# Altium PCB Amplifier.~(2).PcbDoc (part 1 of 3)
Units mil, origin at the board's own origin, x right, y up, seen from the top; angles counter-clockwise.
Board outline 9055.12 x 4724.41 mil, 2 copper layers (Top Layer, Bottom Layer); 154 components, 83 nets, 405 pads, 1525 vias.
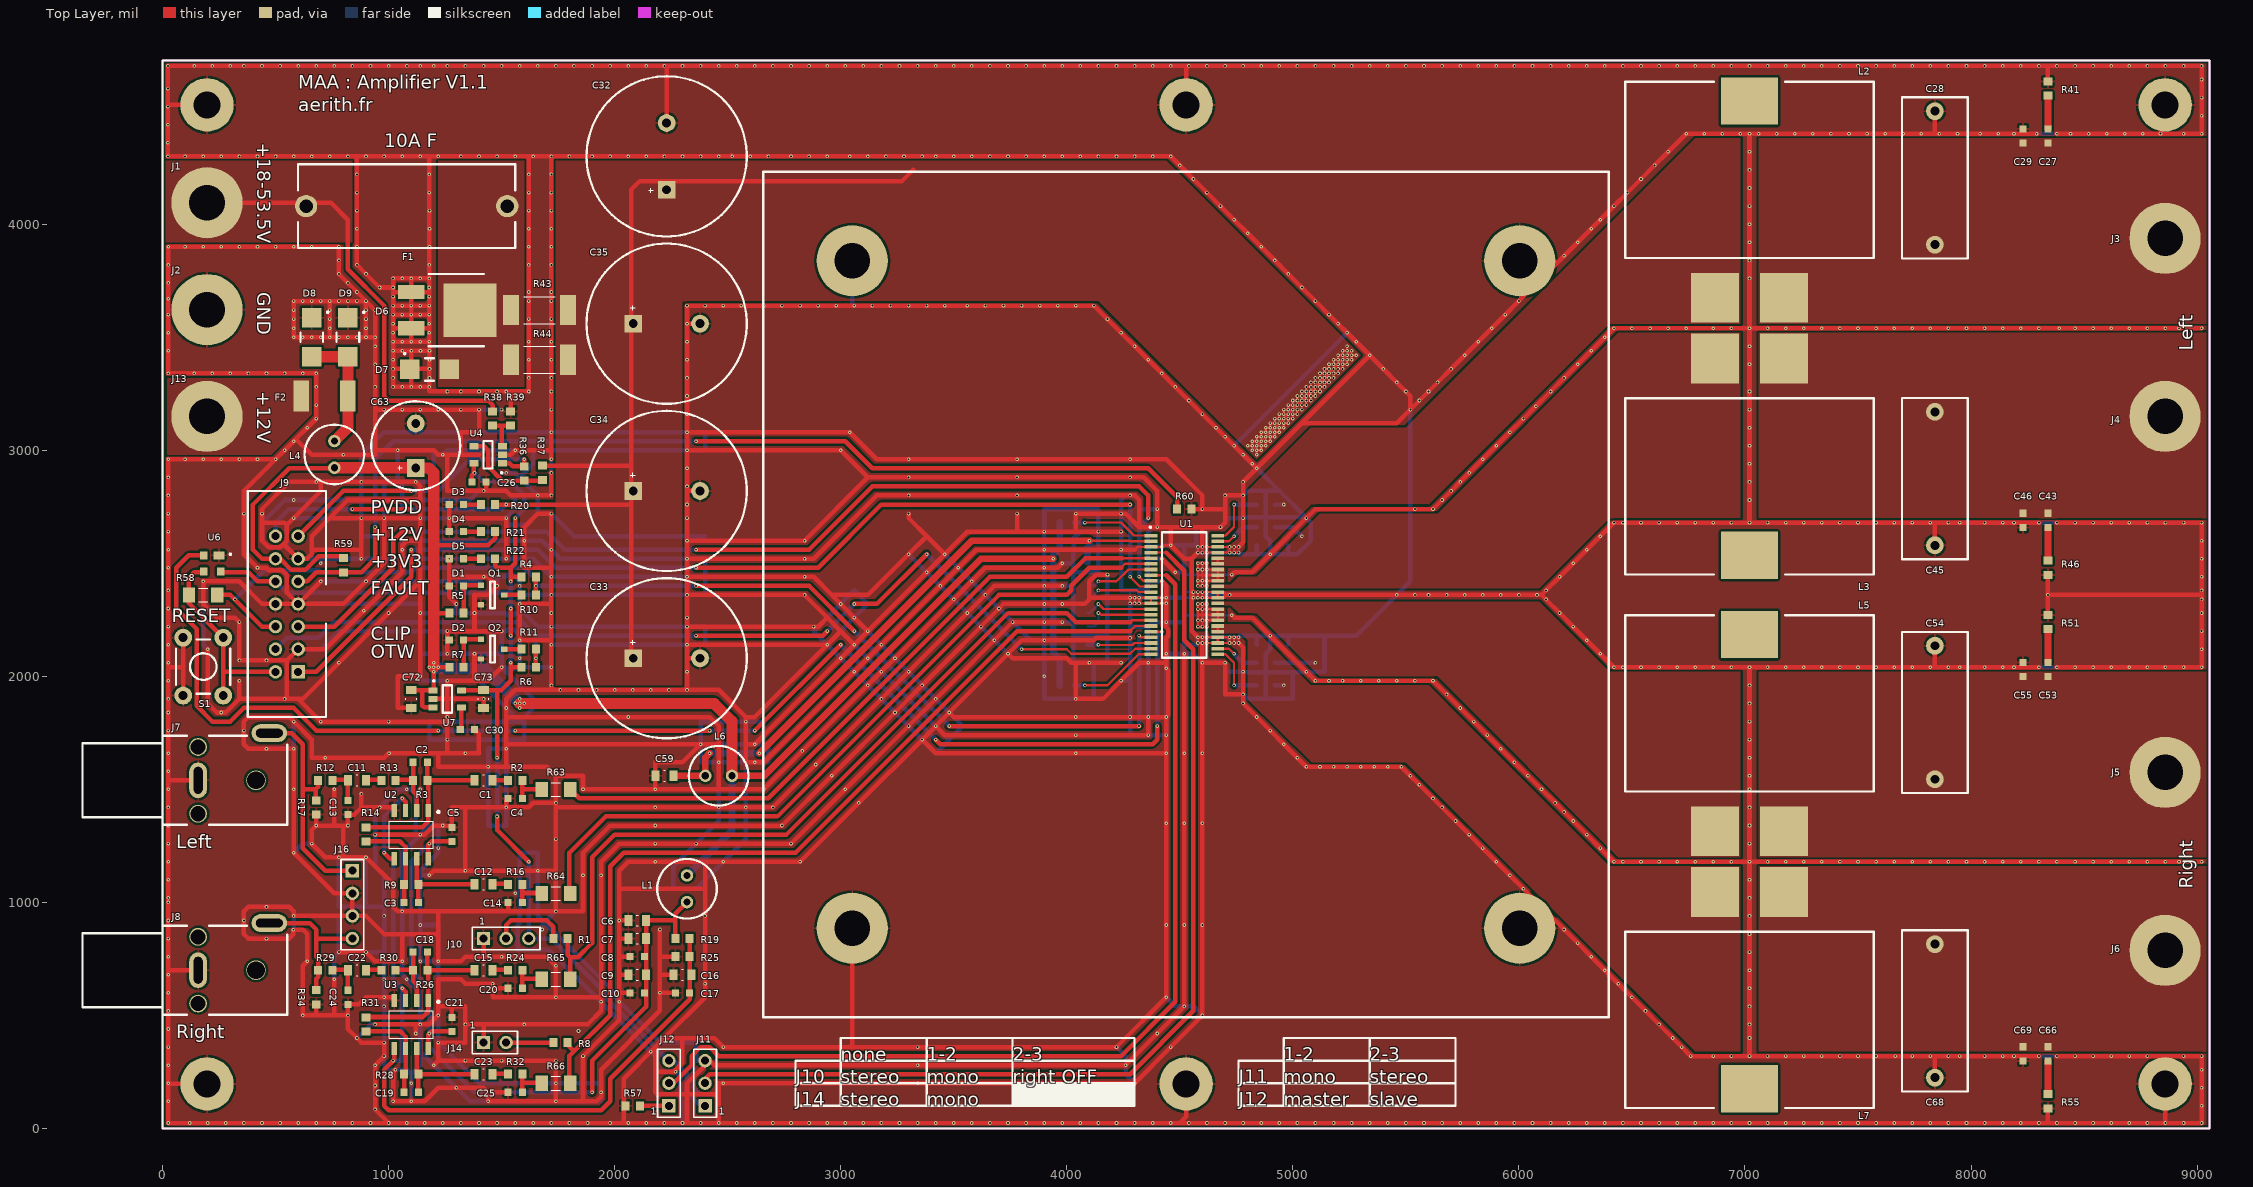
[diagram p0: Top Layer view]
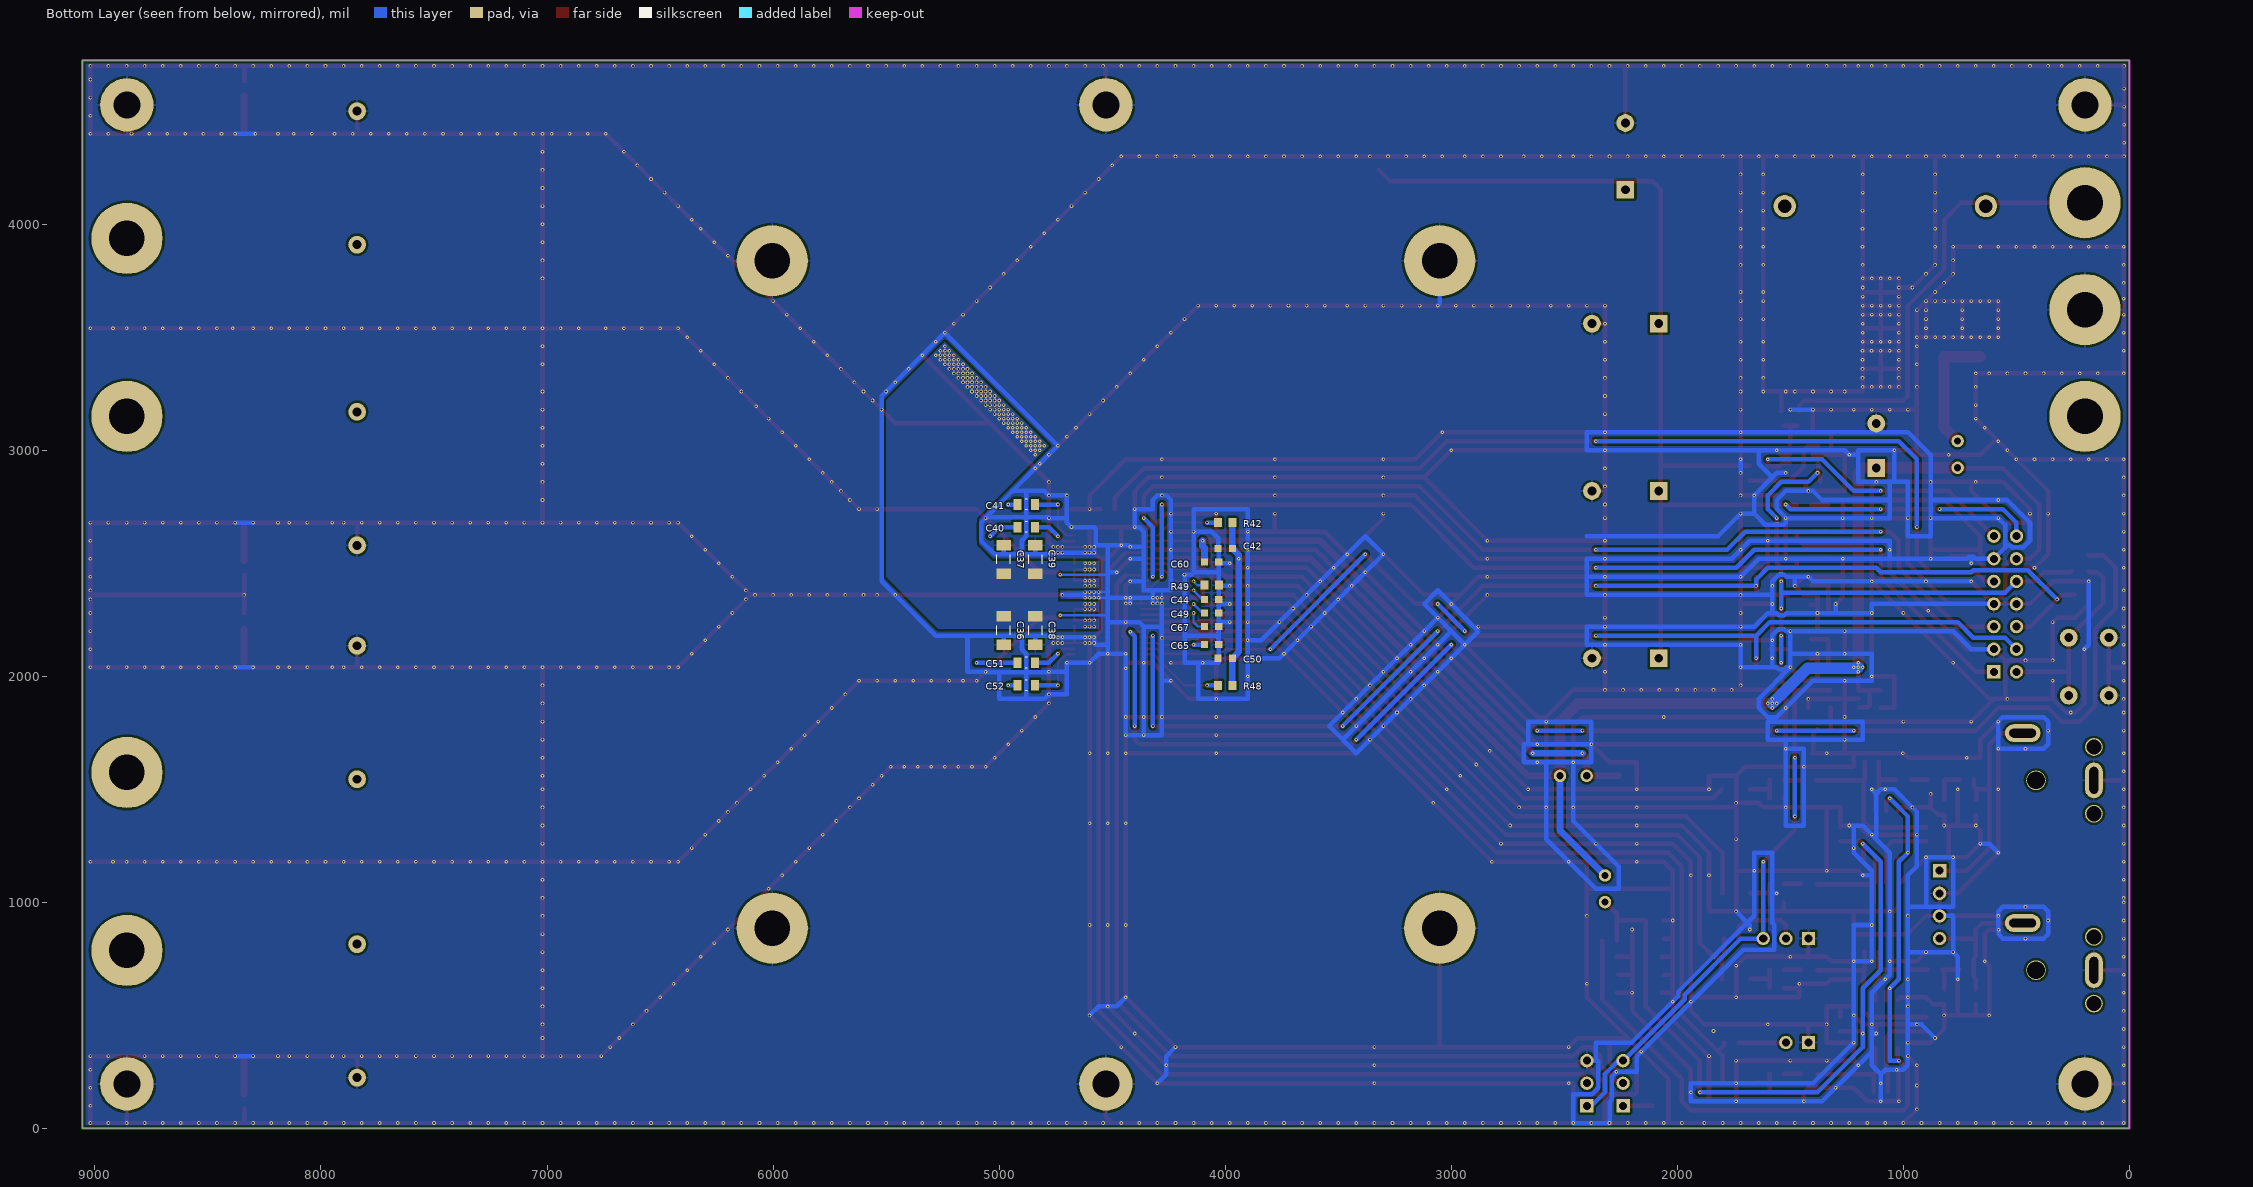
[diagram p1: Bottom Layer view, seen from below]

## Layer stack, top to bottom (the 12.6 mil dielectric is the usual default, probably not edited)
Top Solder: solder mask 0.4, Solder Resist, Dk 3.5
Top Layer: signal copper 1.4
Dielectric 1: dielectric 12.6, FR-4, Dk 4.8
Bottom Layer: signal copper 1.4
Bottom Solder: solder mask 0.4, Solder Resist, Dk 3.5

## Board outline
0,0 9055.12,0 9055.12,4724.41 0,4724.41

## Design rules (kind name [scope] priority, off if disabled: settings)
Clearance [All] p1: gap=10 ignorepadtopadclearanceinfootprint=FALSE except(0: Arc-Hole Track-Hole SMDPad-Hole THPad-Hole Via-Hole Fill-Hole Poly-Hole Region-Hole Text-Hole; 9: Arc-Arc Arc-Track Arc-SMDPad Track-Track Track-SMDPad SMDPad-SMDPad; 29: THPad-THPad)
ComponentClearance U1 [InComponent('U1')] p1: gap=20 collisioncheckmode=3 verticalgap=0 showdistances=TRUE
ComponentClearance [All] p2: gap=19.68 collisioncheckmode=3 verticalgap=3.94 showdistances=TRUE
Height [All] p1: minheight=0 maxheight=2000 prefheight=500
HoleSize [All] p1: absolutevalues=TRUE maxlimit=393.7 minlimit=7.87 maxpercent=80.000 minpercent=20.000
MinimumSolderMaskSliver [All] p1: minsoldermaskwidth=1
PlaneConnect [All] p1: planeconnectstyle=Direct reliefexpansion=20 reliefentries=4 reliefconductorwidth=20 reliefairgap=20
PolygonConnect GND [InNet('GND')] p1: thpad.connectstyle=Relief thpad.reliefconductorwidth=10 thpad.reliefentries=4 thpad.polygonreliefangle="90 Angle" thpad.airgapwidth=10 smdpad.connectstyle=Relief smdpad.reliefconductorwidth=10 smdpad.reliefentries=4 smdpad.polygonreliefangle="90 Angle" smdpad.airgapwidth=10 via.connectstyle=Direct via.reliefconductorwidth=10 via.reliefentries=4 via.polygonreliefangle="90 Angle" via.airgapwidth=10
PolygonConnect DirectConnect [All] p2: connectstyle=Direct reliefconductorwidth=10 reliefentries=4 polygonreliefangle="90 Angle" airgapwidth=10
RoomDefinition Extension [InComponentClass('Extension')] p1: confinementstyle=ConfineIn formatcopy=TRUE lockcomponents=FALSE outline 360,1800 840,1800 840,2840 360,2840
RoomDefinition Amplifier_12V [InComponentClass('Amplifier_12V')] p2: confinementstyle=ConfineIn formatcopy=TRUE lockcomponents=FALSE outline 2140,1420 2600,1420 2600,1700 2140,1700
RoomDefinition Audio_in [InComponentClass('Audio_in')] p3: confinementstyle=ConfineIn formatcopy=TRUE lockcomponents=TRUE outline 760,1220 920,1220 920,760 760,760
RoomDefinition Amplifier_conf [InComponentClass('Amplifier_conf')] p4: confinementstyle=ConfineIn formatcopy=TRUE lockcomponents=TRUE outline 2000,40 2460,40 2460,380 2000,380
RoomDefinition Amplifier_capa [InComponentClass('Amplifier_capa')] p5: confinementstyle=ConfineIn formatcopy=TRUE lockcomponents=TRUE outline 1840,1700 2600,1700 2600,4680 1840,4680
RoomDefinition Thermistance [InComponentClass('Thermistance')] p6: confinementstyle=ConfineIn formatcopy=TRUE lockcomponents=TRUE outline 4460,2840 4580,2840 4580,2700 4460,2700
RoomDefinition Amplifier_core [InComponentClass('Amplifier_core')] p7: confinementstyle=ConfineIn formatcopy=TRUE lockcomponents=TRUE outline 3920,1920 5040,1920 5040,2800 3920,2800
RoomDefinition Status [InComponentClass('Status')] p8: confinementstyle=ConfineIn formatcopy=TRUE lockcomponents=FALSE outline 1160,2800 1160,2000 1700,2000 1700,2800
RoomDefinition Reset [InComponentClass('Reset')] p9: confinementstyle=ConfineIn formatcopy=TRUE lockcomponents=FALSE outline 40,1860 320,1860 320,2560 40,2560
RoomDefinition PVDD_supply [InComponentClass('PVDD_supply')] p10: confinementstyle=ConfineIn formatcopy=TRUE lockcomponents=TRUE outline 0,3260 1840,3260 1840,4280 0,4280
RoomDefinition Pre-amp_supply [InComponentClass('Pre-amp_supply')] p11: confinementstyle=ConfineIn formatcopy=TRUE lockcomponents=FALSE outline 2020,1200 2020,560 2480,560 2480,1200
RoomDefinition Pre-amp_right [InComponentClass('Pre-amp_right')] p12: confinementstyle=ConfineIn formatcopy=TRUE lockcomponents=FALSE outline -380,120 1860,120 1860,960 -380,960
RoomDefinition Pre-amp_left [InComponentClass('Pre-amp_left')] p13: confinementstyle=ConfineIn formatcopy=TRUE lockcomponents=TRUE outline -380,960 1860,960 1860,1800 -380,1800
RoomDefinition Output_D [InComponentClass('Output_D')] p14: confinementstyle=ConfineIn formatcopy=TRUE lockcomponents=FALSE outline 6440,20 9038.72,20 9038.72,1180 6440,1180
RoomDefinition Output_C [InComponentClass('Output_C')] p15: confinementstyle=ConfineIn formatcopy=TRUE lockcomponents=FALSE outline 6440,1180 9040,1180 9040,2360 6440,2360
RoomDefinition Output_B [InComponentClass('Output_B')] p16: confinementstyle=ConfineIn formatcopy=TRUE lockcomponents=FALSE outline 6440,2360 9040,2360 9040,3540 6440,3540
RoomDefinition Output_A [InComponentClass('Output_A')] p17: confinementstyle=ConfineIn formatcopy=TRUE lockcomponents=FALSE outline 6440,3540 9040,3540 9040,4700 6440,4700
RoomDefinition Current_sense [InComponentClass('Current_sense')] p18: confinementstyle=ConfineIn formatcopy=TRUE lockcomponents=TRUE outline 1340,2808.5 1720,2808.5 1720,3268.5 1340,3268.5
RoomDefinition 12V_supply [InComponentClass('12V_supply')] p19: confinementstyle=ConfineIn formatcopy=TRUE lockcomponents=TRUE outline 20,3640 20,2800 1340,2800 1340,3640
RoomDefinition 3V3_supply [InComponentClass('3V3_supply')] p20: confinementstyle=ConfineIn formatcopy=TRUE lockcomponents=TRUE outline 1060,1720 1540,1720 1540,1999.37 1060,1999.37
RoutingVias [All] p1: holewidth=7.87 width=15.75 viastyle="Through Hole" minholewidth=7.87 minwidth=15.75 maxholewidth=15.75 maxwidth=31.5
SilkToSilkClearance [All] p1: silktosilkclearance=0
SolderMaskExpansion [All] p1: expansion=4
Width [All] p1: maxlimit=500 minlimit=10 preferedwidth=10
24 further rules are at their usual default settings.

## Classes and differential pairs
component class Extension: J9 R59
component class Audio_in: J16
component class Amplifier_conf: J11 J12 R57
component class Amplifier_capa: C32 C33 C34 C35
component class Thermistance: R60
component class Amplifier_core: C36 C37 C38 C39 C40 C41 C42 C44 C49 C50 C51 C52 C60 C65 C67 R42 R48 R49 U1
component class Status: D1 D2 D3 D4 D5 Q1 Q2 R4 R5 R6 R7 R10 R11 R20 R21 R22
component class Reset: R58 S1 U6
component class PVDD_supply: D6 D7 F1 J1 J2 R43 R44
component class Pre-amp_supply: C6 C7 C8 C9 C10 C16 C17 L1 R19 R25
component class Pre-amp_right: C15 C18 C19 C20 C21 C22 C23 C24 C25 J8 J10 J14 R1 R8 R24 R26 R28 R29 R30 R31 R32 R34 R65 R66 U3
component class Pre-amp_left: C1 C2 C3 C4 C5 C11 C12 C13 C14 J7 R2 R3 R9 R12 R13 R14 R16 R17 R63 R64 U2
component class Output_D: C66 C68 C69 J6 L7 R55
component class Output_C: C53 C54 C55 J5 L5 R51
component class Output_B: C43 C45 C46 J4 L3 R46
component class Output_A: C27 C28 C29 J3 L2 R41
component class Current_sense: C26 R36 R37 R38 R39 U4
component class 12V_supply: C63 D8 D9 F2 J13 L4
component class 3V3_supply: C30 C72 C73 U7
component class Amplifier_12V: C59 L6

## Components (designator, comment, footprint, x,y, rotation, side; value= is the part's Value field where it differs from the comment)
C1 "10µF" C0805 1420,1540 r0 top
C2 "22pF" C0603 1140,1620 r0 top
C3 "22pF" C0603 1100,1000 r0 top
C4 "100pF" C0603 1560,1460 r180 top
C5 "100nF" C0603 1280,1300 r90 top
C6 "10µF" C0805 2100,920 r180 top
C7 "10µF" C0805 2100,840 r180 top
C8 "100nF" C0603 2100,760 r180 top
C9 "10µF" C0805 2100,680 r180 top
C10 "100nF" C0603 2100,600 r180 top
C11 "10µF" C0805 860,1540 r0 top
C12 "10µF" C0805 1420,1080 r0 top
C13 "100pF" C0603 820,1420 r270 top
C14 "100pF" C0603 1560,1000 r180 top
C15 "10µF" C0805 1420,700 r0 top
C16 "10µF" C0805 2300,680 r180 top
C17 "100nF" C0603 2300,600 r180 top
C18 "22pF" C0603 1140,780 r0 top
C19 "22pF" C0603 1100,160 r0 top
C20 "100pF" C0603 1560,620 r180 top
C21 "100nF" C0603 1280,460 r90 top
C22 "10µF" C0805 860,700 r0 top
C23 "10µF" C0805 1420,240 r0 top
C24 "100pF" C0603 820,580 r270 top
C25 "100pF" C0603 1560,160 r180 top
C26 "100nF" C0603 1400,2860 r0 top
C27 "10nF 100V" C0603 8340,4390 r90 top
C28 "680nF 250V" CAP_15 7840,4204.72 r90 top
C29 "1nF 100V" C0603 8230,4390 r90 top
C30 "10nF 100V" C0603 1348.54,1765 r0 top
C32 "2200µF 63V" CAP_18X7.5 2230,4300 r90 top
C33 "2200µF 63V" CAP_18X7.5 2230,2080 r0 top
C34 "2200µF 63V" CAP_18X7.5 2230,2820 r0 top
C35 "2200µF 63V" CAP_18X7.5 2230,3560 r0 top
C36 "1µF 100V" C1206 4980,2202.99 r270 bottom
C37 "1µF 100V" C1206 4980,2517.01 r90 bottom
C38 "1µF 100V" C1206 4840,2202.99 r270 bottom
C39 "1µF 100V" C1206 4840,2517.01 r90 bottom
C40 "33nF 100V" C0805 4880,2660 r180 bottom
C41 "33nF 100V" C0805 4880,2760 r180 bottom
C42 "100nF" C0603 4000,2565.45 r0 bottom
C43 "10nF 100V" C0603 8340,2690 r270 top
C44 "1µF" C0603 4060,2340 r0 bottom
C45 "680nF 250V" CAP_15 7840,2874.72 r270 top
C46 "1nF 100V" C0603 8230,2690 r270 top
C49 "1µF" C0603 4060,2280 r0 bottom
C50 "100nF" C0603 4000,2080 r0 bottom
C51 "33nF 100V" C0805 4880,2060 r0 bottom
C52 "33nF 100V" C0805 4880,1960 r0 bottom
C53 "10nF 100V" C0603 8340,2030 r90 top
C54 "680nF 250V" CAP_15 7840,1840 r90 top
C55 "1nF 100V" C0603 8230,2030 r90 top
C59 "10µF" C0805 2220,1560 r180 top
C60 "100nF" C0603 4060,2506.26 r180 bottom
C63 "1000µF 16V" CAP_10x5 1120,3020 r90 top
C65 "100nF" C0603 4060,2140 r180 bottom
C66 "10nF 100V" C0603 8340,330 r270 top
C67 "1µF" C0603 4060,2220 r0 bottom
C68 "680nF 250V" CAP_15 7840,520 r270 top
C69 "1nF 100V" C0603 8230,330 r270 top
C72 "10µF" C0805 1100,1900 r270 top
C73 "10µF" C0805 1420,1900 r270 top
D1 "Red" C0603 1300,2400 r180 top
D2 "Yellow" C0603 1300,2160 r180 top
D3 "Green" C0603 1300,2760 r180 top
D4 "Green" C0603 1300,2640 r180 top
D5 "Green" C0603 1300,2520 r180 top
D6 "15A" DPAK 1300,3620 r270 top
D7 "56V" DO-214AC 1181.01,3357.43 r0 top
D8 "12V" DO-214AC 660,3500 r270 top
D9 "2A" DO-214AC 820,3500 r270 top
F1 "10A F" "FUSE OLDER" 1080,4080 r0 top
F2 "1.1A PTC" MC362XX 716.46,3240 r0 top
J1 "M4 screw" HOLE_4#1 196.85,4094.49 r0 top
J2 "M4 screw" HOLE_4#2 196.85,3582.68 r0 top
J3 "M4 screw" HOLE_4#1 8858.27,3937.01 r0 top
J4 "M4 screw" HOLE_4#1 8858.27,3149.61 r0 top
J5 "M4 screw" HOLE_4#1 8858.27,1574.8 r0 top
J6 "M4 screw" HOLE_4#1 8858.27,787.4 r0 top
J7 "RCA" CON_RCA 0,1540 r90 top
J8 "RCA" CON_RCA 0,700 r90 top
J9 "2x7x2.54" CON_header_2x7 550,2320 r90 top
J10 "3x2.54" HDR1X3 1420,840 r0 top
J11 "3x2.54" HDR1X3 2400,100 r90 top
J12 "3x2.54" HDR1X3 2240,100 r90 top
J13 "M4 screw" HOLE_4#1 196.85,3149.61 r0 top
J14 "2x2.54" HDR1X2 1420,380 r0 top
J16 "4x2.54 lock" HDR1X4 840,1140 r270 top
L1 "10µH 1A" SELF_6.7x3 2320,1060 r270 top
L2 "SER2915L-682KL" SELF_SMD_SER2915X 7020,4240 r0 top
L3 "SER2915L-682KL" SELF_SMD_SER2915X 7020,2840 r180 top
L4 "10µH 1A" SELF_6.7x3 760,2981.58 r270 top
L5 "SER2915L-682KL" SELF_SMD_SER2915X 7020,1880 r0 top
L6 "10µH 1A" SELF_6.7x3 2460,1560 r180 top
L7 "SER2915L-682KL" SELF_SMD_SER2915X 7020,480 r180 top
Q1 "BSH108" SOT-23-GSD 1460,2360 r0 top
Q2 "BSH108" SOT-23-GSD 1460,2120 r0 top
R1 "10k" R0603 1760,840 r0 top
R2 "100" R0603 1560,1540 r180 top
R3 "10k" R0603 1140,1540 r180 top
R4 "10k" R0603 1620,2440 r0 top
R5 "1k" R0603 1300,2280 r0 top
R6 "10k" R0603 1620,2040 r0 top
R7 "1k" R0603 1300,2040 r0 top
R8 "10k" R0603 1760,380 r180 top
R9 "10k" R0603 1100,1080 r180 top
R10 "100" R0603 1620,2360 r0 top
R11 "100" R0603 1620,2120 r0 top
R12 "100" R0603 720,1540 r180 top
R13 "10k" R0603 1000,1540 r180 top
R14 "10k" R0603 900,1300 r90 top
R16 "100" R0603 1560,1080 r180 top
R17 "100k" R0603 680,1420 r270 top
R19 "10k" R0603 2300,840 r0 top
R20 "4k7" R0603 1440,2760 r180 top
R21 "1k" R0603 1440,2640 r180 top
R22 "100" R0603 1440,2520 r180 top
R24 "100" R0603 1560,700 r180 top
R25 "10k" R0603 2300,760 r180 top
R26 "10k" R0603 1140,700 r180 top
R28 "10k" R0603 1100,240 r180 top
R29 "100" R0603 720,700 r180 top
R30 "10k" R0603 1000,700 r180 top
R31 "10k" R0603 900,460 r90 top
R32 "100" R0603 1560,240 r180 top
R34 "100k" R0603 680,580 r270 top
R36 "470k" R0603 1600,2897.01 r270 top
R37 "10k" R0603 1680,2900 r270 top
R38 "10k" R0603 1460,3140 r270 top
R39 "470k" R0603 1540,3140 r90 top
R41 "3R3" R0603 8340,4600 r90 top
R42 "3R3" R0603 4000,2680 r180 bottom
R43 "10m 1W" R2512 1667.22,3620 r0 top
R44 "10m 1W" R2512 1667.22,3400 r0 top
R46 "3R3" R0603 8340,2480 r270 top
R48 "3R3" R0603 4000,1960 r180 bottom
R49 "30k" R0603 4060,2403.13 r0 bottom
R51 "3R3" R0603 8340,2240 r90 top
R55 "3R3" R0603 8340,120 r270 top
R57 "10k" R0603 2080,100 r0 top
R58 "R0" R1206 180,2360 r0 top
R59 "30k" R0603 800,2491.5 r270 top
R60 "10k CTN" R0603 4520,2740 r180 top
R63 "R0" R1206 1740,1500 r180 top
R64 "R0" R1206 1740,1040 r180 top
R65 "R0" R1206 1740,660 r180 top
R66 "R0" R1206 1740,200 r180 top
S1 "SW-PB" BP_PCB 180,2043.05 r90 top
U1 "TPA3255" TSSOP-44 4520,2360 r0 top locked
U2 "OPA1652" SOIC-8 1100,1300 r270 top
U3 "OPA1652" SOIC-8 1100,460 r270 top
U4 "MCP6001" SOT-23-5 1440,2980 r270 top
U6 "STM811T" SOT143-4 220,2500 r270 top
U7 "LP2985-33DBVR" SOT-23-5 1260,1900 r90 top

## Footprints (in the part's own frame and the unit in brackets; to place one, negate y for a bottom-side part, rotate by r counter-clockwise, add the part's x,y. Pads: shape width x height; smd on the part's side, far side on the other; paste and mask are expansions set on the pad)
BP_PCB [mm] "Mini bouton poussoir sur PCB"
  round 2 hole 1: 1(-3.25,2.25) 1(3.25,2.25) 2(-3.25,-2.25) 2(3.25,-2.25)
  silkscreen extent -3.05,-3.05 3.05,3.05, body extent -3.5,-3 3.5,3, height 5
C0603 [mm]
  rect 0.8x0.8 smd: 1(-0.8,0) 2(0.8,0)
  body extent -0.8,-0.4 0.8,0.4, height 0.8
C0805 [mm]
  rect 0.9x1.2 smd: 1(-1,0) 2(1,0)
  silkscreen extent -0.1,-0.6 0.1,0.6, body extent -1,-0.6 1,0.6, height 1.2
C1206 [mm]
  rect 1.2x1.6 smd: 1(-1.6,0) 2(1.6,0)
  silkscreen extent -0.51,-0.76 0.51,0.76, body extent -1.6,-0.8 1.6,0.8, height 1.6
CAP_10x5 [mm] "Capacitor throug hole dia=10mm, H=16mm, spacing=5mm"
  rect 2x2 hole 1: 1(-2.5,0)
  round 2 hole 1: 2(2.5,0)
  silkscreen extent -5,-5 5,5, body extent -5,-5 5,5, height 16
CAP_15 [mm] "Film capacitor, step 15mm"
  round 2 hole 1: 1(-7.5,0) 2(7.5,0)
  silkscreen extent -9.05,-3.7 9.05,3.7, body extent -9.05,-3.7 9.05,3.7, height 19
CAP_18X7.5 [mm] "Capacitor throug hole dia=18mm, H=35.5mm, spacing=7.5mm"
  rect 2x2 hole 1: 1(-3.75,0)
  round 2 hole 1: 2(3.75,0)
  silkscreen extent -9,-9 9,9, body extent -9,-9 9,9, height 35.5
CON_header_2x7 [mm] "2x7x2.54mm with lock"
  rect 1.5x1.5 hole 0.9: 1(-7.62,-1.27)
  round 1.5 hole 0.9: 2(-7.62,1.27) 3(-5.08,-1.27) 4(-5.08,1.27) 5(-2.54,-1.27) 6(-2.54,1.27) 7(0,-1.27) 8(0,1.27) 9(2.54,-1.27) 10(2.54,1.27) 11(5.08,-1.27) 12(5.08,1.27) 13(7.62,-1.27) 14(7.62,1.27)
  silkscreen extent -12.7,-4.4 12.7,4.4, body extent -12.7,-4.4 12.7,4.4, height 9
CON_RCA [mm] "JEITA RC-5231"
  oval 4x2 hole 1 slot 3 at 0 deg: 1(0,-4)
  oval 2x4 hole 1 slot 3 at 90 deg: 2(5.3,-12)
  round 2 hole 1.7: ""(-3.75,-4) ""(3.75,-4)
  round 2.2 hole 2: ""(0,-10.5)
  silkscreen extent -5,-14 5,9, body extent -5,-14 5,9, height 13
DO-214AC [mm]
  rect 2.2x2.2 smd: 1(-2.2,0) 2(2.2,0)
  silkscreen extent -2.89,-1.27 0.51,1.88, body extent -2.75,-1.4 2.75,1.4, height 2.3
DPAK [mm] "DPAK"
  rect 1.6x3 smd: 1(-2.032,-5.08) 3(2.032,-5.08)
  rect 6x6 smd: 2(0,1.524)
  silkscreen extent -4.06,-3.11 4.06,3.11, body extent -3.36,-3.11 3.36,3.11, height 2.38
"FUSE OLDER" [mm] "MULTICOMP - MCHTC-100M - 5X20mm"
  round 2.5 hole 1.5: 1(-11.3,0) 2(11.3,0)
  silkscreen extent -12.2,-4.7 12.2,4.7, body extent -12.2,-4.7 12.2,4.7, height 13.3
HDR1X2 [mm] "Connector; Header; 2 Position"
  rect 1.5x1.5 hole 0.9: 1(0,0)
  round 1.5 hole 0.9: 2(2.54,0)
  silkscreen extent -1.27,-1.27 3.81,1.27
HDR1X3 [mm] "Connector; Header; 3 Position"
  rect 1.5x1.5 hole 0.9: 1(0,0)
  round 1.5 hole 0.9: 2(2.54,0) 3(5.08,0)
  silkscreen extent -1.27,-1.27 6.35,1.27
HDR1X4 [mm] "Connector; Header; 4 Position"
  rect 1.5x1.5 hole 0.9: 1(0,0)
  round 1.5 hole 0.9: 2(2.54,0) 3(5.08,0) 4(7.62,0)
  silkscreen extent -1.27,-1.27 8.89,1.27
HOLE_4#1 [mm] "Hole for M4 screw"
  round 8 hole 4: 1(0,0)
HOLE_4#2 [mm] "Hole for M4 screw"
  round 8 hole 4: 1(0,1)
MC362XX [mm] "Fuse PTC"
  rect 1.78x3.5 smd: 1(-2.615,0) 2(2.615,0)
  body extent -2.36,-1.71 2.36,1.71, height 1.55
R0603 [mm] "0.1W"
  rect 0.9x1 smd: 1(-0.8,0) 2(0.8,0)
  body extent -0.8,-0.4 0.8,0.4, height 0.45
R1206 [mm] "0.25W"
  rect 1.4x1.7 smd: 1(-1.6,0) 2(1.6,0)
  silkscreen extent -0.51,-0.76 0.51,0.76, body extent -1.6,-0.8 1.6,0.8, height 0.6
R2512 [mm] "1W"
  rect 1.8x3.4 smd: 1(-3.2,0) 2(3.2,0)
  silkscreen extent -1.78,-1.52 1.78,1.52, body extent -3.2,-1.6 3.2,1.6, height 0.6
SELF_6.7x3 [mm] "Inductor throug hole dia=6.7mm, H=10mm, spacing=3mm"
  round 1.4 hole 0.8: 1(-1.5,0) 2(1.5,0)
  silkscreen extent -3.35,-3.35 3.35,3.35, body extent -3.35,-3.35 3.35,3.35, height 10
SELF_SMD_SER2915X [mm] "Coilcraft shielded power inductor SER2900"
  rect 5.4x5.6 smd: 1(-3.9,-14.36) 2(3.9,-14.36)
  rect 6.35x5.3 smd: 3(0,7.73)
  silkscreen extent -13.95,-9.9 13.95,9.9, body extent -13.95,-11 13.95,11, height 15.36
SOIC-8 [mm] "8-Pin Plastic Narrow Body Small Outline Integrated Circuit 1.27 mm Pitch, IPC Medium Density"
  rect 1.5x0.6 smd: 1(-2.7,1.905) 2(-2.7,0.635) 3(-2.7,-0.635) 4(-2.7,-1.905) 5(2.7,-1.905) 6(2.7,-0.635) 7(2.7,0.635) 8(2.7,1.905)
  silkscreen extent -2.66,-2.45 1.52,3.17, body extent -1.95,-2.45 1.95,2.45, height 1.76
SOT143-4 [mm]
  rect 0.9x1.2 smd: 1(-0.9,0.75)
  rect 0.9x0.8 smd: 2(-0.9,-0.95) 3(0.9,-0.95) 4(0.9,0.95)
  silkscreen extent -1.12,1.93 -0.92,2.13, body extent -0.7,-1.52 0.7,1.52, height 1.12
SOT-23-5 [mm] "SOT-23 5pins"
  rect 0.7x1 smd: 1(0.95,1.6) 2(0,1.6) 3(-0.95,1.6) 4(-0.95,-1.6) 5(0.95,-1.6)
  silkscreen extent -1.55,-0.51 2.13,1.62, body extent -1.55,-0.9 1.55,0.9, height 1.45
SOT-23-GSD [mm] "Transistor"
  rect 0.7x0.6 smd: 1(1.3,0) 2(-1.3,1.1) 3(-1.3,-1.1)
  silkscreen extent -0.25,-1.5 0.25,1.5, body extent -0.7,-1.5 0.7,1.5, height 1.1
TSSOP-44 [mm]
  rect 1.45x0.4 smd: 1(-3.75,6.667) 2(-3.75,6.032) 3(-3.75,5.397) 4(-3.75,4.763) 5(-3.75,4.127) 6(-3.75,3.492) 7(-3.75,2.857) 8(-3.75,2.222) 9(-3.75,1.587) 10(-3.75,0.953) 11(-3.75,0.318) 12(-3.75,-0.318) 13(-3.75,-0.953) 14(-3.75,-1.587) 15(-3.75,-2.222) 16(-3.75,-2.857) 17(-3.75,-3.492) 18(-3.75,-4.127) 19(-3.75,-4.763) 20(-3.75,-5.397) 21(-3.75,-6.032) 22(-3.75,-6.667) 23(3.75,-6.667) 24(3.75,-6.032) 25(3.75,-5.397) 26(3.75,-4.763) 27(3.75,-4.127) 28(3.75,-3.492) 29(3.75,-2.857) 30(3.75,-2.222) 31(3.75,-1.587) 32(3.75,-0.953) 33(3.75,-0.318) 34(3.75,0.318) 35(3.75,0.953) 36(3.75,1.587) 37(3.75,2.222) 38(3.75,2.857) 39(3.75,3.492) 40(3.75,4.127) 41(3.75,4.763) 42(3.75,5.397) 43(3.75,6.032) 44(3.75,6.667)
  silkscreen extent -3.91,-7.05 2.5,7.72, body extent -3.1,-7.05 3.1,7.05, height 1

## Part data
C1 C2 C3 C4 C5 C6 C7 C8 C9 C10 C11 C12 C13 C14 C15 C16 C17 C18 C19 C20 C21 C22 C23 C24 C25 C26 C27 C28 C29 C30 C36 C37 C38 C39 C40 C41 C42 C43 C44 C45 C46 C49 C50 C51 C52 C53 C54 C55 C59 C60 C63 C65 C66 C67 C68 C69 C72 C73: library part Cap, "Capacitor"
C32 C33 C34 C35: library part "Cap Pol1", "Polarized Capacitor (Radial)"
D1 D2 D3 D4 D5: library part LED2, "Typical RED, GREEN, YELLOW, AMBER GaAs LED"
D6 D9: library part "D Schottky", "Schottky Diode"
D7 D8: library part "Diode TVS", "TVS diode"
F1: library part "Fuse 1", "Fuse"
F2: library part "Fuse Thermal", "Thermal Fuse"
J1 J2 J3 J4 J5 J6 J13: library part Plug
J7 J8: "RCA Phono Jack, Right Angle, Thru-Hole, Snap-In"
J9: library part "Header 7X2", "Header, 7-Pin, Dual row"
J10 J11 J12: library part "Header 3", "Header, 3-Pin"
J14: library part "Header 2", "Header, 2-Pin"
J16: library part "Header 4", "Header, 4-Pin"
L1 L2 L3 L4 L5 L6 L7: library part "Inductor Iron", "Magnetic-Core Inductor"
Q1 Q2: library part NMOS-2, "N-Channel Power MOSFET"
R1 R2 R3 R4 R5 R6 R7 R8 R9 R10 R11 R12 R13 R14 R16 R17 R19 R20 R21 R22 R24 R25 R26 R28 R29 R30 R31 R32 R34 R36 R37 R38 R39 R41 R42 R43 R44 R46 R48 R49 R51 R55 R57 R58 R59 R63 R64 R65 R66: library part Res2, "Resistor"
R60: library part "Res Varistor", "Varistor (Voltage-Sensitive Resistor)"
S1: "Switch"
U1: library part TPA3251D2DDVR, "150W Stereo/300W MONO PurePath HD Analog-input Power Stage, DDV0044D"
U2 U3: "Low Noise and Distortion, General-Purpose, FET-Input Audio Op Amps"
U4: library part "Op Amp", "FET Operational Amplifier"
U6: library part STM8xx, "Voltage monitor"
U7: library part LP2985-x, "150mA, Low-Noise, 350mVdrop max, LDO voltage regulator"

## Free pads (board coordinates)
  round 236.22 hole 118.11: ""(196.85,196.85) ""(196.85,4527.56) ""(4527.56,196.85) ""(4527.56,4527.56) ""(8858.27,196.85) ""(8858.27,4527.56)
  round 314.96 hole 157.48: ""(3051.18,885.83) ""(3051.18,3838.58) ""(6003.94,885.83) ""(6003.94,3838.58)

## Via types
v1: diameter 15.75, hole 7.87, Top Layer to Bottom Layer, 1525 vias

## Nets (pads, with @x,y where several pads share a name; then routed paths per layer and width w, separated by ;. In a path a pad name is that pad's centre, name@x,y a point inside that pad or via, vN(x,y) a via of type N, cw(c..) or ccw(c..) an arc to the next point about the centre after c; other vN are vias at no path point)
+3V3: C26.1 C73.1 J9.10 J10.3 J11.1 J12.3 R4.1 R6.1 R22.1 U4.5 U6.4 U7.5 | length 5249.9
  Top Layer w20: U6.4@257.4,2464.57 261.97,2460 380,2460 420,2420 J9.10@500,2420 ; U7.5@1322.99,1937.4 1480,1937.4 ; C26.1@1368.5,2860 1368.5,2888.5 1377.01,2897.01 U4.5@1377.01,2942.6 ; R22.1@1471.5,2520 1471.5,2488.5 1480,2480 1540,2480 ; v1(1480,1380) 1480,1320 v1(1620,1180) ; v1(1480,1640) 1480,1937.4 ; v1(1540,2060) 1540,2040 ; v1(1540,2180) v1(1540,2300) ; v1(1540,2420) 1540,2440 ; v1(1560,2700) 1560,2500 1540,2480 ; R6.1@1588.5,2040 1540,2040 ; R4.1@1588.5,2440 1540,2440 ; 1480,1937.4 1497.4,1937.4 1540,1980 1540,2040 ; 1540,2440 1540,2480
  Bottom Layer w20: J9.10@500,2420 549.53,2370.47 1540,2370.47 ; v1(1380,2900) 1420,2860 1540,2860 1600,2800 1600,2740 v1(1560,2700) ; v1(1480,1380) v1(1480,1640) ; v1(1540,2060) v1(1540,2180) ; v1(1540,2300) 1540,2370.47 ; v1(1540,2420) 1540,2370.47 ; v1(1620,1180) J10.3@1620,840 1719.42,840 1967.87,591.55 1967.87,572.13 J12.3@2240,300 2261.01,300 2320,241.01 2320,160 2380,100 J11.1@2400,100
+12V: C42.1 C50.1 C63.1 C72.1 J9.12 L1.1 L4.2 L6.1 R5.1 R7.1 R21.1 R42.2 R48.2 R59.1 U7.1 U7.3 | length 7916.4
  Top Layer w20: L4.2@760,2922.53 757.47,2920 560,2920 400,2760 400,2560 440,2520 J9.12@500,2520 520,2520 569.53,2470.47 631.48,2470.47 672.13,2511.11 672.13,2511.55 691.58,2531 791.99,2531 R59.1@800,2522.99 ; C72.1@1100,1939.37 1101.97,1937.4 1149.49,1937.4 ; U7.3@1197.01,1862.6 1157.4,1862.6 1149.49,1870.51 1149.49,1937.4 ; 1200,2280 R5.1@1268.5,2280 ; 1200,2580 1440,2580 1471.5,2611.5 R21.1@1471.5,2640 ; R7.1@1268.5,2040 v1(1220,2040) v1(1200,2040) v1(1200,2020) 1200,1940.39 U7.1@1197.01,1937.4 1149.49,1937.4
  Top Layer w30: C63.1@1119.05,2922.53 C63.1@1120,2921.57 ; L6.1@2519.06,1560 2660,1560 3620,2520 v1(3940,2520)
  Top Layer w50: L4.2@760,2922.53 C63.1@1119.05,2922.53 ; C63.1@1120,2921.57 1178.43,2921.57 1200,2900 1200,2580 1200,2280 v1(1200,2060) v1(1200,2040) ; v1(1580,1880) v1(1600,1880) 2440,1880 2519.06,1800.94 L6.1@2519.06,1560
  Bottom Layer w30: L1.1@2320,1119.06 2519.06,1318.11 L6.1@2519.06,1560 ; R48.2@3968.5,1960 C50.1@3968.5,2080 3940,2108.5 3940,2536.94 C42.1@3968.5,2565.45 R42.2@3968.5,2680
  Bottom Layer w50: v1(1200,2040) 1204,2036 1424,2036 v1(1580,1880)
  other v1: 1580,1860 1560,1880 1580,1900 1180,2040
+12V-PRE: C5.1 C6.1 C7.1 C8.1 C9.1 C10.1 C21.1 L1.2 R19.1 U2.8 U3.8 | length 3291.7
  Top Layer w20: U3.8@1175,355.2 1175,415 v1(1180,420) 1190,430 C21.1@1280,430 ; U2.8@1175,1195.2 1175,1255 v1(1180,1260) 1190,1270 C5.1@1280,1270 ; v1(1900,160) 1900,300 2139.37,539.37 C9.1@2139.37,680 C7.1@2139.37,840 C6.1@2139.37,920 2268.5,920 ; R19.1@2268.5,830 2268.5,920 ; L1.2@2320,1000.94 2268.5,949.45 2268.5,920
  Bottom Layer w20: v1(1180,1260) 1100,1180 1100,700 1180,620 v1(1180,420) 1180,360 1380,160 v1(1900,160)
+12Vin: F2.1 J13.1
C\L\I\P\_\O\T\W\: J9.4 R6.2 R11.2 U1.21 | length 4468.2
  Top Layer w10: v1(3800,2120) 4000,2120 4020,2100 4280,2100 4302.5,2122.5 U1.21@4372.36,2122.5
  Top Layer w20: R6.2@1651.5,2040 v1(1651.5,2080) R11.2@1651.5,2120 ; v1(2360,2180) 2920,2180 v1(2940,2200) ; v1(3060,2320) 3160,2320 v1(3380,2540)
  Bottom Layer w20: J9.4@500,2120 550.47,2170.47 690.47,2170.47 760,2240 1591.5,2240 1651.5,2180 ; v1(1651.5,2080) 1651.5,2180 ; v1(2360,2180) 1651.5,2180 ; v1(2940,2200) v1(3060,2320) ; v1(3380,2540) 3771,2149 3771,2147.99 3798.99,2120 v1(3800,2120)
Current: J9.13 R36.1 U4.1 | length 1275.2
  Top Layer w20: J9.13@600,2620 800,2820 v1(1100,2820) ; U4.1@1502.99,2942.6 1534.09,2942.6 1548.19,2928.5 R36.1@1600,2928.5 v1(1600,2960)
  Bottom Layer w20: v1(1100,2820) 1220,2820 1360,2960 v1(1600,2960)
F\A\U\L\T\: J9.6 R4.2 R10.2 R58.2 U1.19 | length 5223
  Top Layer w10: v1(4320,2180) 4327.5,2172.5 U1.19@4372.36,2172.5
  Top Layer w20: R58.2@242.99,2360 300,2360 440,2220 J9.6@500,2220 ; R10.2@1651.5,2360 v1(1651.5,2400) R4.2@1651.5,2440 ; v1(2360,2400) 2860,2400 v1(3060,2200) ; v1(3480,1780) v1(4320,1780)
  Bottom Layer w20: v1(320,2340) 449.53,2469.53 690.47,2469.53 700,2460 1100,2460 1120,2480 1600,2480 1651.5,2428.5 v1(1651.5,2400) v1(2360,2400) ; v1(3060,2200) v1(3480,1780) ; v1(4320,1780) v1(4320,2180)
FREQ_ADJ: J12.2 U1.8 | length 4417.4
  Top Layer w10: U1.8@4372.36,2447.5 4440,2447.5
  Top Layer w20: J12.2@2240,200 2260,200 2340,280 2340,320 2380,360 2420,360 2460,320 4240,320 4480,560 4480,2407.5 4440,2447.5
